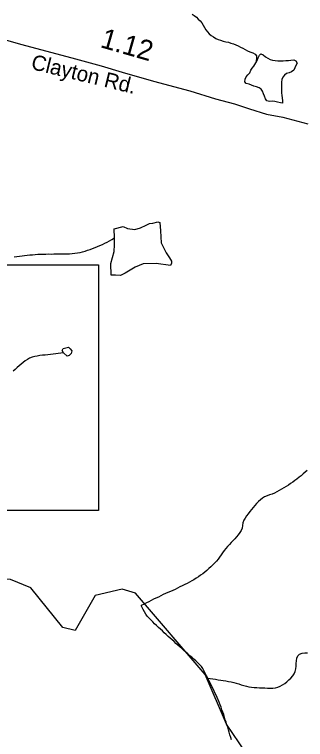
# Model space of a CAD drawing. Extents: x 1950930 to 2061844, y 904556 to 1017002.
# Drawn here: x 1973365 to 1975173, y 965651 to 970163 of the extents above; entities that cross this region are included whole.
import ezdxf

# ---------------------------------------------------------------- set-up
doc = ezdxf.new("R2010")
doc.units = 0
for name, color, linetype in [('Exist Hydrographic Creek Single Shore', 7, 'Continuous'), ('Exist Hydrographic Misc Water Feature', 7, 'Continuous'), ('Exist Road Primary US Structure Standard Bridge CELL', 7, 'Continuous'), ('Exist Road Secondary Structure Standard Bridge Number Label', 7, 'Continuous'), ('Exist Road Secondary Type 51 Attributed', 7, 'Continuous'), ('Exist Road Secondary Type 51 Label', 7, 'Continuous')]:
    doc.layers.add(name, color=color, linetype=linetype)

msp = doc.modelspace()

# ---------------------------------------------------------------- linework, layer by layer
at = {"layer": 'Exist Hydrographic Creek Single Shore'}
msp.add_lwpolyline([(1974840.4, 965513.3), (1974682.3, 965746.3), (1974549.2, 966054.4), (1974116.4, 966562.2), (1974033.3, 966586.8), (1973866.4, 966547.6), (1973741.3, 966330.2), (1973666.3, 966348.2), (1973466.4, 966595.3), (1973341.3, 966647.1), (1972966.2, 966654.8), (1972841.4, 966723), (1972441.3, 967272.9), (1972100.3, 967988.8), (1971909.4, 968199.5), (1971617.4, 968373), (1971400.2, 968666.4), (1971284.4, 969056.1), (1971176.3, 970082.3), (1971135.3, 970207.9)], dxfattribs=at)
at = {"layer": 'Exist Hydrographic Misc Water Feature'}
for points in [[(1974469.7, 970166.3), (1974482.4, 970156.3), (1974495.3, 970146.1), (1974507.4, 970135.2), (1974519.3, 970124.4), (1974530, 970111.8), (1974538.4, 970097.6), (1974546.2, 970082.7), (1974554.6, 970068.6), (1974563.8, 970055.3), (1974575.3, 970043.6), (1974588.2, 970032.6), (1974601.9, 970023.4), (1974616.1, 970014.9), (1974630.9, 970008), (1974646, 970002.7), (1974661.8, 969997.4), (1974677.8, 969993.9), (1974694, 969990.2), (1974710, 969985.8), (1974725.6, 969981.5), (1974740.8, 969975.3), (1974755.5, 969968.4), (1974770.3, 969960.7), (1974785.1, 969953.1), (1974799.4, 969945.4), (1974814, 969937.7), (1974828.5, 969930), (1974845.3, 969923.9), (1974860.5, 969916.2), (1974869.3, 969905.4), (1974869.9, 969889.8), (1974865, 969862)], [(1974865, 969862), (1974872.6, 969877.4), (1974880, 969894.5), (1974887.8, 969909.1), (1974896.8, 969918.8), (1974909.7, 969912.8), (1974924.3, 969900.1), (1974938.4, 969891.6), (1974953, 969883.9), (1974968.6, 969878.7), (1974984.8, 969876.7), (1975001.2, 969875.5), (1975017.6, 969875.2), (1975034, 969875.7), (1975050.6, 969876.3), (1975066.8, 969877.5), (1975083.2, 969878.8), (1975100, 969880.9), (1975113.3, 969875.7), (1975120.7, 969860), (1975113.5, 969846.1), (1975107.4, 969831.6), (1975100.8, 969816.9), (1975087.1, 969807.4), (1975071.9, 969801.1), (1975056.3, 969795.7), (1975043, 969786.1), (1975032.5, 969773.2), (1975026.6, 969758.6), (1975024.6, 969741.3), (1975023.7, 969724.9), (1975023.5, 969708.5), (1975024.1, 969692.1), (1975024.8, 969675.7), (1975026, 969659.3), (1975028.2, 969643.6), (1975031.1, 969625.5), (1975030.9, 969611.5), (1975017.2, 969612.7), (1975000.2, 969617.2), (1974982.7, 969622.4), (1974966.3, 969622.8), (1974949.7, 969621.5), (1974933.7, 969625.1), (1974924.9, 969638.4), (1974918.3, 969654.1), (1974912.2, 969669.9), (1974907.1, 969685.6), (1974898.7, 969698.8), (1974885.3, 969707.3), (1974869.3, 969712.6), (1974853.1, 969717.9), (1974838, 969723.9), (1974822.4, 969729.1), (1974805.1, 969734.4), (1974795.7, 969743.7), (1974798.6, 969760), (1974805.1, 969776.3), (1974816, 969788.3), (1974826.7, 969800.4), (1974833.2, 969815.9), (1974842.5, 969829.6), (1974852.7, 969841.7), (1974865, 969862)], [(1973986.6, 968774.1), (1973984.1, 968828.3), (1974040.1, 968844.4), (1974068, 968830.7), (1974112.1, 968824.9), (1974148, 968835.6), (1974183.8, 968852.1), (1974203.5, 968862.4), (1974225.7, 968864.3), (1974255.4, 968872.7), (1974269.3, 968868.3), (1974272, 968816.7), (1974276.7, 968742.6), (1974307.3, 968678.9), (1974327.6, 968649.7), (1974341.7, 968627.3), (1974339.9, 968615.9), (1974333.9, 968601.1), (1974246.2, 968612.8), (1974163.9, 968612.1), (1974114.3, 968591), (1974052.8, 968552.9), (1974023.1, 968538.7), (1973992.9, 968540.1), (1973965, 968539.9), (1973964.2, 968613.8), (1973985.6, 968688), (1973987.2, 968729.8), (1973986.6, 968774.1)], [(1973379.8, 968657), (1973396, 968660), (1973412.2, 968662.1), (1973428.4, 968664.2), (1973444.8, 968665.5), (1973461.4, 968666.9), (1973477.6, 968668.2), (1973494, 968669.4), (1973510.4, 968670.8), (1973526.9, 968671.3), (1973543.1, 968671.7), (1973559.5, 968672.2), (1973576.1, 968672.7), (1973592.5, 968672.4), (1973608.7, 968672.8), (1973625.3, 968673.3), (1973641.7, 968673), (1973658.1, 968673.4), (1973674.7, 968673.1), (1973690.9, 968672.7), (1973707.3, 968674), (1973723.7, 968675.4), (1973739.9, 968677.5), (1973756.1, 968679.6), (1973772.3, 968682.5), (1973788.3, 968686.3), (1973804.3, 968691), (1973819.9, 968695.6), (1973835.5, 968700.9), (1973850.8, 968706.3), (1973866, 968712.6), (1973881.2, 968719.7), (1973895.9, 968725.9), (1973911.1, 968732.2), (1973926.1, 968739.3), (1973940.9, 968746.3), (1973955.2, 968754.2), (1973969.1, 968763), (1973986.6, 968774.1)], [(1973363.6, 968654.1), (1973379.8, 968657)], [(1973670.2, 968056.9), (1973660.8, 968071.2), (1973667.9, 968084.1), (1973683.5, 968089.5), (1973699.9, 968092.5), (1973711.4, 968081.5), (1973720.8, 968069.1), (1973717.1, 968052.7), (1973705.7, 968040.6), (1973691.7, 968036), (1973670.2, 968056.9)], [(1973670.2, 968056.9), (1973653.8, 968054.9), (1973637.4, 968053.6), (1973621.2, 968051.5), (1973605, 968049.3), (1973588.4, 968048), (1973572.2, 968045.9), (1973556, 968043.8), (1973539.8, 968042.5), (1973523.2, 968040.3), (1973507, 968037.4), (1973491.2, 968034.5), (1973475.2, 968029.9), (1973459.4, 968024.4), (1973445.2, 968016.5), (1973431.9, 968007.7), (1973418.8, 967997.4), (1973406.1, 967986.9), (1973393.6, 967976.6), (1973381.3, 967965.4), (1973369.2, 967954.1), (1973357.5, 967942.8)], [(1975182.9, 967325.7), (1975170.8, 967314.5), (1975158.5, 967303.4), (1975145.9, 967292.9), (1975133.2, 967282.6), (1975120.3, 967272.1), (1975107.4, 967262.6), (1975094.1, 967252.9), (1975080.5, 967243.4), (1975066.8, 967234.7), (1975052.8, 967226), (1975038.9, 967217.2), (1975024.8, 967208.4), (1975010.6, 967200.5), (1974996.3, 967191.8), (1974981.7, 967184.7), (1974966.5, 967178.5), (1974950.7, 967173.1), (1974934.7, 967167.6), (1974919.6, 967160.5), (1974905.6, 967152.7), (1974893.3, 967143.1), (1974881.4, 967131.8), (1974869.9, 967119.7), (1974858.7, 967107.6), (1974847.6, 967095.7), (1974836.9, 967082.7), (1974826.7, 967069.8), (1974816.6, 967056.1), (1974807.2, 967043.2), (1974798, 967029.4), (1974789.4, 967015.6), (1974784.8, 967000.1), (1974782.8, 966982.9), (1974780.1, 966966.6), (1974774.2, 966951.9), (1974765, 966938.2), (1974755.1, 966925.1), (1974744.9, 966913.2), (1974733.8, 966900.2), (1974722.7, 966888.1), (1974711.6, 966876), (1974700.4, 966864), (1974689.1, 966851.9), (1974678, 966839), (1974667.6, 966826.9), (1974657.9, 966813.2), (1974648.5, 966800.3), (1974639.5, 966786.5), (1974629.8, 966772.8), (1974619.8, 966759.8), (1974608.5, 966748.6), (1974596.6, 966736.5), (1974584.7, 966725.2), (1974572.4, 966714.9), (1974560.1, 966703.6), (1974547.2, 966693.2)], [(1974547.2, 966693.2), (1974534.5, 966682.8), (1974521.1, 966673.2), (1974508, 966663.7), (1974494.5, 966654.1), (1974480.5, 966645.4), (1974466.6, 966637.5), (1974452, 966629.6), (1974437.5, 966621.6), (1974422.7, 966614.6), (1974408, 966607.5), (1974393.2, 966600.4), (1974378.4, 966592.5), (1974363.7, 966585.4), (1974348.7, 966579.2), (1974333.7, 966573), (1974318.6, 966565.9), (1974303.6, 966559.6), (1974288.8, 966552.5), (1974273.9, 966545.4), (1974259.3, 966537.5), (1974244.5, 966530.5), (1974230, 966523.3), (1974215.4, 966515.5), (1974200.7, 966508.4), (1974186.1, 966500.5), (1974171.3, 966493.4), (1974153.3, 966483.9)], [(1974565.6, 966033.2), (1974557.9, 966047.3), (1974550.1, 966062.2), (1974542.9, 966077.1), (1974535.3, 966092), (1974526.3, 966105.4), (1974515.4, 966117), (1974503.9, 966128.8), (1974492.2, 966140.5), (1974479.9, 966151.4), (1974467.4, 966162.4), (1974454.9, 966172.5), (1974442.6, 966184.2), (1974430.5, 966195.1), (1974418, 966205.2), (1974405.7, 966216.2), (1974393.2, 966227.2), (1974380.9, 966238), (1974368.6, 966248.9), (1974356.5, 966259.9), (1974344.2, 966270.7), (1974332.1, 966281.7), (1974320.2, 966292.6), (1974308.1, 966304.4), (1974295.8, 966315.2), (1974283.9, 966326.2), (1974272, 966337.9), (1974260.1, 966348.7), (1974248.2, 966360.5), (1974236.1, 966371.5), (1974224.4, 966383.2), (1974212.5, 966394.9), (1974201.5, 966406.6), (1974190.6, 966418.4), (1974180.6, 966431.7), (1974173, 966445.8), (1974165.8, 966460.7), (1974153.3, 966483.9)], [(1974565.6, 966033.2), (1974581.8, 966030.3), (1974598, 966028.4), (1974614.2, 966025.6), (1974630.4, 966022.8), (1974646.8, 966020.8), (1974662.8, 966018), (1974679, 966015.2), (1974695.2, 966012.5), (1974711.4, 966009.6), (1974727.2, 966006), (1974743.2, 966001.6), (1974758.8, 965996.4), (1974774.6, 965992), (1974790.6, 965986.6), (1974806.2, 965983), (1974822.2, 965979.4), (1974838.4, 965976.7), (1974854.6, 965974.6), (1974871, 965973.5), (1974887.4, 965972.4), (1974903.8, 965972), (1974920.2, 965971.7), (1974936.6, 965971.3), (1974953.4, 965970.9), (1974970, 965970.6), (1974986.6, 965972), (1975002.2, 965975.8), (1975017, 965982), (1975031.3, 965990.7), (1975045.1, 966000.3), (1975057.6, 966010.6), (1975070.1, 966021.9), (1975082.6, 966033.1), (1975093.9, 966046.1), (1975103.1, 966059), (1975109.4, 966073.6), (1975112.9, 966089.9), (1975115, 966106.3), (1975116.2, 966124.3), (1975117.9, 966140.7), (1975120.1, 966157), (1975124.8, 966171.7), (1975135.3, 966182.1), (1975152.3, 966187.6), (1975169.7, 966189.6), (1975185.9, 966191)], [(1974713.1, 965648.6), (1974708.8, 965664.3), (1974704.3, 965679.9), (1974699.7, 965695.6), (1974695.2, 965711.2), (1974690.3, 965726.9), (1974685.4, 965742.6), (1974680.3, 965758.4), (1974675.3, 965774.1), (1974670.2, 965789.8), (1974665.1, 965805.5), (1974660, 965821.1), (1974654.4, 965836), (1974648.7, 965851.7), (1974643.2, 965867.5), (1974637.2, 965882.4), (1974630.9, 965897.2), (1974624.3, 965912.2), (1974617.5, 965927.1), (1974610.6, 965941.9), (1974603.4, 965956.9), (1974596.2, 965971.8), (1974589, 965986.7), (1974582, 966001.7), (1974574.7, 966015.7), (1974565.6, 966033.2)]]:
    msp.add_lwpolyline(points, dxfattribs=at)
at = {"layer": 'Exist Road Secondary Structure Standard Bridge Number Label'}
msp.add_lwpolyline([(1971309.9, 968605.6), (1973886.4, 968605.6), (1973886.4, 967076.4), (1971309.9, 967076.4)], close=True, dxfattribs=at)
at = {"layer": 'Exist Road Secondary Type 51 Attributed'}
msp.add_lwpolyline([(1972660.2, 970195.3), (1972784.4, 970156.8), (1972924.4, 970111.2), (1973097.7, 970063.9), (1973270.1, 970015.8), (1973410.5, 969975.9), (1973744.8, 969886.6), (1973904.1, 969842.8), (1974035.1, 969803.6), (1974228.9, 969748), (1974454.7, 969688.4), (1974614, 969637.6), (1974731.7, 969606.5), (1974826.2, 969575.9), (1974930.3, 969542.6), (1975031.8, 969524.2), (1975187.1, 969483.5)], dxfattribs=at)

# ---------------------------------------------------------------- texts
at = {"layer": 'Exist Road Primary US Structure Standard Bridge CELL'}
msp.add_text('1.12', height=125, rotation=343.9904, dxfattribs=at).set_placement((1973892.4, 969961.1))
at = {"layer": 'Exist Road Secondary Type 51 Label'}
msp.add_text('Clayton Rd.', height=95, rotation=346.3398, dxfattribs=at).set_placement((1973462.9, 969824.7))

doc.saveas('drawing.dxf')
